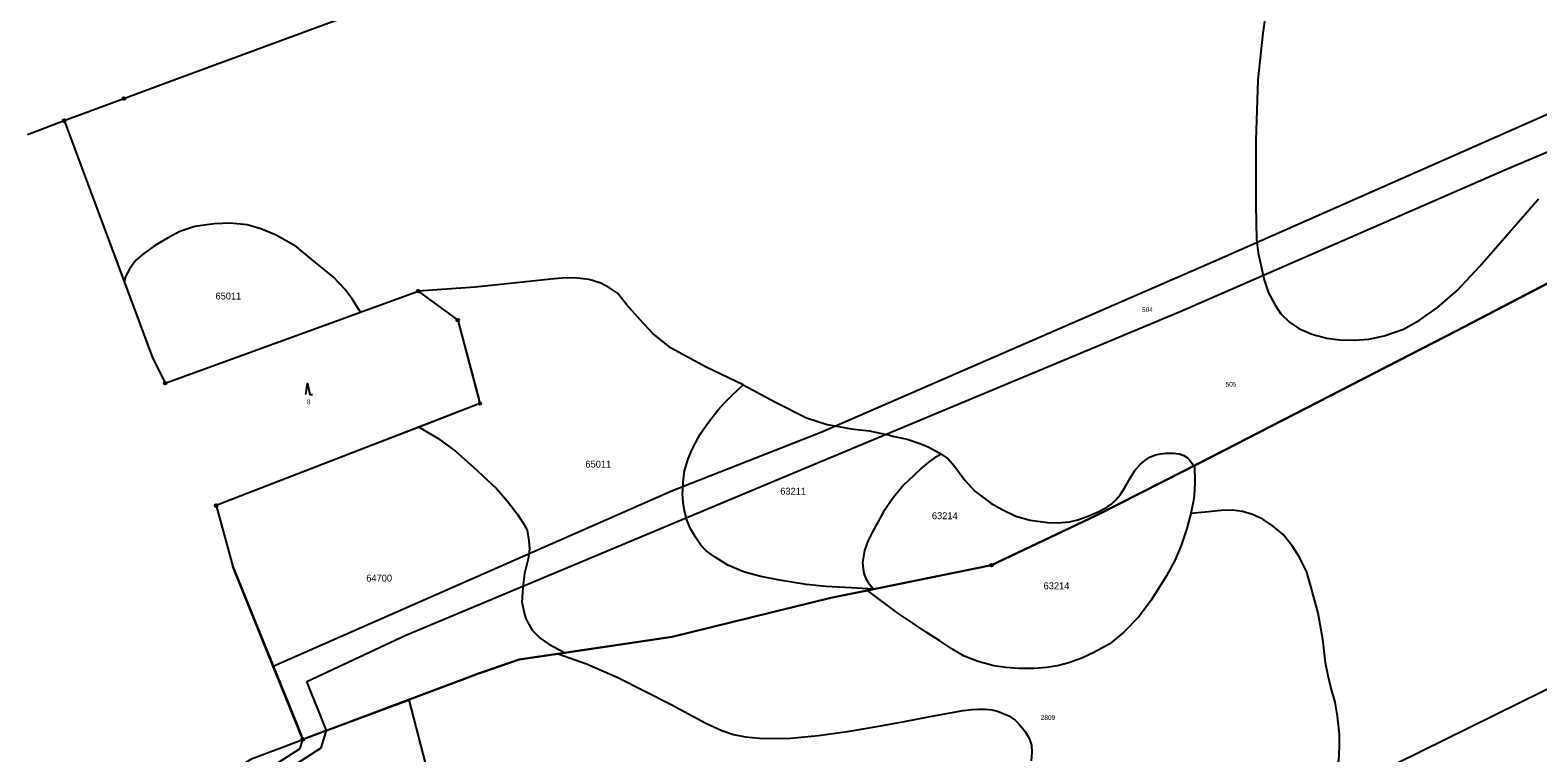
# Model space of a CAD drawing. Extents: x -546762 to -540209, y -1046851 to -1035694.
# Drawn here: x -543378 to -542834, y -1037889 to -1037629 of the extents above; entities that cross this region are included whole.
import ezdxf

# ---------------------------------------------------------------- set-up
doc = ezdxf.new("R2010")
doc.units = 0
for name, color, linetype in [('Vrstva 1', 7, 'Continuous'), ('Vrstva 13', 7, 'Continuous'), ('Vrstva 16', 7, 'Continuous'), ('Vrstva 18', 7, 'Continuous'), ('Vrstva 24', 7, 'Continuous'), ('Vrstva 25', 7, 'Continuous'), ('Vrstva 52', 7, 'Continuous'), ('Vrstva 53', 7, 'Continuous')]:
    doc.layers.add(name, color=color, linetype=linetype)

msp = doc.modelspace()

# ---------------------------------------------------------------- linework, layer by layer
at = {"layer": 'Vrstva 1'}
for points in [[(-542805.97, -1037647.97), (-542951.27, -1037712.12)], [(-543365.34, -1037661.2), (-543333.73, -1037746.28)], [(-542846.53, -1037679.1), (-542798.39, -1037658.61)], [(-542963.29, -1037729.97), (-542846.53, -1037679.1)], [(-542951.27, -1037712.12), (-543092.34, -1037773.37)], [(-543328.98, -1037755.78), (-543237.86, -1037722.64)], [(-543237.86, -1037722.64), (-543223.51, -1037733.09)], [(-543102.79, -1037788.23), (-542963.29, -1037729.97)], [(-543223.51, -1037733.09), (-543215.56, -1037763.13)], [(-543333.73, -1037746.28), (-543328.98, -1037755.78)], [(-543215.56, -1037763.13), (-543310.65, -1037799.88)], [(-543092.34, -1037773.37), (-543146.21, -1037794.52)], [(-543242.28, -1037846.48), (-543102.79, -1037788.23)], [(-543146.21, -1037794.52), (-543290.05, -1037857.78)], [(-543310.65, -1037799.88), (-543304.67, -1037821.75)], [(-543290.05, -1037857.78), (-543304.67, -1037821.75)], [(-543277.99, -1037863.18), (-543242.28, -1037846.48)], [(-543279.38, -1037884.08), (-543290.05, -1037857.78)], [(-542823.6, -1037862.41), (-542885.41, -1037892.84)], [(-543270.81, -1037880.88), (-543277.99, -1037863.18)], [(-543211.01, -1037985.66), (-543241.09, -1037869.78)], [(-543280.35, -1037887.31), (-543279.38, -1037884.08)], [(-543272.73, -1037887.17), (-543270.81, -1037880.88)], [(-543330.94, -1037919.79), (-543280.35, -1037887.31)], [(-543327.84, -1037922.56), (-543272.73, -1037887.17)]]:
    msp.add_lwpolyline(points, dxfattribs=at)
at = {"layer": 'Vrstva 13'}
for points in [[(-543327.47, -1037647.05), (-543267.73, -1037625.19)], [(-543343.92, -1037653.2), (-543327.47, -1037647.05)], [(-543365.34, -1037661.2), (-543343.92, -1037653.2)], [(-543378.65, -1037666.17), (-543365.34, -1037661.2)], [(-542863.73, -1037736.88), (-542811.28, -1037709.61)], [(-542863.73, -1037736.88), (-542811.28, -1037709.61)], [(-542863.73, -1037736.88), (-542943.06, -1037777.75)], [(-542863.73, -1037736.88), (-542943.06, -1037777.75)], [(-542943.06, -1037777.75), (-542961.6, -1037787.22)], [(-542943.06, -1037777.75), (-542961.6, -1037787.22)], [(-542961.6, -1037787.22), (-542993.59, -1037803.39)], [(-542961.6, -1037787.22), (-542993.59, -1037803.39)], [(-542993.59, -1037803.39), (-543031.22, -1037821.3)], [(-542993.59, -1037803.39), (-543031.22, -1037821.3)], [(-543031.22, -1037821.3), (-543089.11, -1037833.1)], [(-543031.22, -1037821.3), (-543089.11, -1037833.1)], [(-543089.11, -1037833.1), (-543146.35, -1037847.19)], [(-543089.11, -1037833.1), (-543146.35, -1037847.19)], [(-543146.35, -1037847.19), (-543201.5, -1037855.31)], [(-543146.35, -1037847.19), (-543201.5, -1037855.31)], [(-543201.5, -1037855.31), (-543211.84, -1037858.86)], [(-543201.5, -1037855.31), (-543211.84, -1037858.86)], [(-543216.44, -1037860.58), (-543241.09, -1037869.78)], [(-543216.44, -1037860.58), (-543241.09, -1037869.78)], [(-543213.18, -1037859.36), (-543216.44, -1037860.58)], [(-543213.18, -1037859.36), (-543216.44, -1037860.58)], [(-543211.84, -1037858.86), (-543213.18, -1037859.36)], [(-543211.84, -1037858.86), (-543213.18, -1037859.36)], [(-543270.81, -1037880.88), (-543241.09, -1037869.78)], [(-543270.81, -1037880.88), (-543241.09, -1037869.78)], [(-543297.93, -1037891.04), (-543279.38, -1037884.08)], [(-543297.93, -1037891.04), (-543279.38, -1037884.08)], [(-543270.81, -1037880.88), (-543279.38, -1037884.08)], [(-543270.81, -1037880.88), (-543279.38, -1037884.08)]]:
    msp.add_lwpolyline(points, dxfattribs=at)
at = {"layer": 'Vrstva 24'}
for centre, radius in [((-543343.92, -1037653.2), 0.5), ((-543343.92, -1037653.2), 0.1), ((-543365.34, -1037661.2), 0.5), ((-543365.34, -1037661.2), 0.1), ((-543237.86, -1037722.64), 0.5), ((-543237.86, -1037722.64), 0.1), ((-543223.51, -1037733.09), 0.5), ((-543223.51, -1037733.09), 0.1), ((-543328.98, -1037755.78), 0.5), ((-543328.98, -1037755.78), 0.1), ((-543215.56, -1037763.13), 0.5), ((-543215.56, -1037763.13), 0.1), ((-543310.65, -1037799.88), 0.5), ((-543310.65, -1037799.88), 0.1), ((-543031.22, -1037821.3), 0.5), ((-543031.22, -1037821.3), 0.1), ((-543279.38, -1037884.08), 0.5), ((-543279.38, -1037884.08), 0.1)]:
    msp.add_circle(centre, radius, dxfattribs=at)
at = {"layer": 'Vrstva 25'}
msp.add_lwpolyline([(-543278.36, -1037759.86), (-543277.66, -1037755.86), (-543276.86, -1037759.86), (-543275.86, -1037759.86)], dxfattribs=at)
at = {"layer": 'Vrstva 52'}
for points in [[(-543365.34, -1037661.2), (-543343.92, -1037653.2), (-543327.47, -1037647.05), (-543267.73, -1037625.19), (-543235.81, -1037616.25), (-543203.18, -1037606.26), (-543165.36, -1037594.45), (-543131.14, -1037580.09), (-543110.06, -1037571.25), (-543094.01, -1037561.29), (-543066.03, -1037551.41), (-543055.79, -1037547.74), (-542980.98, -1037519.01), (-542991.19, -1037498.05), (-543009.21, -1037454.54), (-543031.79, -1037392.1), (-543041.26, -1037370.55), (-543046.29, -1037359.6)], [(-542931.78, -1037618.19), (-542933.54, -1037629.67), (-542935.24, -1037646.53), (-542935.95, -1037668.36), (-542935.95, -1037691.46), (-542935.81, -1037704.07), (-542935.21, -1037708.82), (-542935.19, -1037708.92), (-542934.24, -1037713.19), (-542933.59, -1037715.88), (-542932.95, -1037718.54), (-542931.41, -1037723.24), (-542929.22, -1037727.45), (-542926.96, -1037730.85), (-542923.88, -1037733.76), (-542920.56, -1037736.03), (-542915.79, -1037738.14), (-542910.44, -1037739.51), (-542905.75, -1037740.16), (-542900.57, -1037740.32), (-542895.23, -1037739.92), (-542889.72, -1037738.7), (-542882.76, -1037736.28), (-542877.01, -1037733.12), (-542870.54, -1037728.5), (-542863.42, -1037722.43), (-542855.24, -1037713.6), (-542834.1, -1037689.32)], [(-542597.71, -1037761.19), (-542601.64, -1037747.66), (-542602.11, -1037746.04), (-542619.97, -1037671.06), (-542636.93, -1037631.27), (-542645.13, -1037634.51), (-542696.78, -1037655.45), (-542744.49, -1037676.78), (-542808.69, -1037708.26), (-542863.73, -1037736.88), (-542943.06, -1037777.75), (-542953.82, -1037783.29), (-542958.58, -1037785.7)], [(-542958.13, -1037785.47), (-542953.82, -1037783.29), (-542943.06, -1037777.75), (-542863.73, -1037736.88), (-542808.69, -1037708.26), (-542744.49, -1037676.78), (-542696.78, -1037655.45), (-542645.13, -1037634.51), (-542636.93, -1037631.27), (-542619.97, -1037671.06), (-542602.11, -1037746.04), (-542601.64, -1037747.66), (-542601.46, -1037748.27)], [(-543365.34, -1037661.2), (-543343.8, -1037719.18)], [(-543258.59, -1037730.18), (-543261.69, -1037725.27), (-543264.32, -1037721.93), (-543268.39, -1037717.53), (-543276.11, -1037711.24), (-543281.84, -1037706.54), (-543289, -1037702.4), (-543294.49, -1037700.18), (-543299.42, -1037698.74), (-543305.63, -1037698.19), (-543311.36, -1037698.34), (-543318.28, -1037699.3), (-543323.77, -1037701.13), (-543328.15, -1037703.52), (-543332.52, -1037706.07), (-543336.66, -1037709.01), (-543339.68, -1037711.64), (-543341.91, -1037714.66), (-543343.26, -1037717.37), (-543343.8, -1037719.18)], [(-543343.8, -1037719.18), (-543333.73, -1037746.28)], [(-543120.76, -1037756.4), (-543134.12, -1037750), (-543146.65, -1037743.17), (-543153.2, -1037738.02), (-543157.85, -1037732.98), (-543162.73, -1037727.41), (-543166.04, -1037723.39), (-543168.9, -1037721.47), (-543172.01, -1037719.8), (-543176.22, -1037718.45), (-543180.6, -1037717.89), (-543184.58, -1037717.81), (-543189.99, -1037718.29), (-543197.87, -1037719.17), (-543217.28, -1037721.24), (-543237.86, -1037722.64)], [(-543258.59, -1037730.18), (-543237.86, -1037722.64)], [(-543237.86, -1037722.64), (-543223.51, -1037733.09), (-543216.02, -1037761.39), (-543215.56, -1037763.13), (-543237.45, -1037771.59)], [(-543333.73, -1037746.28), (-543328.98, -1037755.78), (-543259.57, -1037730.54)], [(-543259.57, -1037730.54), (-543258.59, -1037730.18)], [(-543073.78, -1037829.98), (-543081.82, -1037829.5), (-543090.89, -1037828.95), (-543098.06, -1037828.31), (-543107.68, -1037826.78), (-543114.41, -1037825.37), (-543120.27, -1037823.83), (-543126.23, -1037821.28), (-543130.77, -1037818.5), (-543134.03, -1037816.14), (-543136.02, -1037814.07), (-543137.85, -1037811.29), (-543139.76, -1037808.18), (-543141.04, -1037805), (-543141.91, -1037801.81), (-543142.39, -1037798.79), (-543142.47, -1037797.21), (-543142.55, -1037795.52), (-543142.51, -1037794.4), (-543142.39, -1037791.38), (-543141.83, -1037787.32), (-543140.72, -1037783.34), (-543139.52, -1037780.4), (-543137.85, -1037777.21), (-543136.18, -1037774.19), (-543134.11, -1037771.01), (-543132.36, -1037768.7), (-543129.74, -1037765.35), (-543127.43, -1037762.89), (-543124.72, -1037760.1), (-543120.76, -1037756.4)], [(-543120.76, -1037756.4), (-543109.06, -1037762.67), (-543097.92, -1037768.25), (-543090.48, -1037770.71), (-543081.73, -1037772.23), (-543078.75, -1037772.55), (-543075.21, -1037772.94), (-543068.05, -1037774.54), (-543066.83, -1037774.81), (-543061.6, -1037775.97), (-543056.67, -1037777.56), (-543053.8, -1037778.83), (-543050.06, -1037780.82), (-543049.36, -1037781.31)], [(-543237.45, -1037771.59), (-543252.53, -1037777.41), (-543254.36, -1037778.12), (-543310.65, -1037799.88), (-543304.67, -1037821.75), (-543281.19, -1037879.42), (-543280.44, -1037881.35), (-543279.38, -1037884.08)], [(-543237.45, -1037771.59), (-543230.61, -1037775.69), (-543224.34, -1037780.29), (-543218.07, -1037785.86), (-543209.62, -1037793.72), (-543205.8, -1037798.1), (-543202.22, -1037802.88), (-543200.07, -1037805.9), (-543198.56, -1037808.77), (-543197.92, -1037812.59), (-543197.77, -1037815.62), (-543198.22, -1037819.08), (-543199.48, -1037824.37), (-543200.17, -1037829.39), (-543200.45, -1037834.78), (-543200.37, -1037835.16), (-543199.58, -1037839), (-543198.99, -1037840.5), (-543198.38, -1037842.02), (-543196.79, -1037844.73), (-543193.85, -1037847.68), (-543190.76, -1037849.75), (-543184.92, -1037852.87)], [(-543049.36, -1037781.31), (-543051.86, -1037782.76), (-543053.91, -1037784.26), (-543056.46, -1037786.44), (-543059.33, -1037789.14), (-543062.83, -1037792.41), (-543066.73, -1037797.1), (-543070.15, -1037802.12), (-543074.25, -1037809.61), (-543075.79, -1037812.62), (-543077.02, -1037816.03), (-543077.39, -1037818.21), (-543077.7, -1037820.35), (-543077.52, -1037822.62), (-543077.2, -1037824.35), (-543076.57, -1037826.08), (-543075.68, -1037827.58)], [(-543049.36, -1037781.31), (-543046.88, -1037783.05), (-543044.64, -1037785.64), (-543040.88, -1037790.66), (-543037.26, -1037794.7), (-543031.55, -1037799.01), (-543027.37, -1037801.24), (-543022.46, -1037803.72), (-543017.36, -1037805.13), (-543011.04, -1037805.94), (-543007.45, -1037806.03), (-543003.18, -1037805.67), (-543000.09, -1037804.94), (-542996.13, -1037803.53), (-542992.81, -1037802.08), (-542989.86, -1037800.58), (-542987.95, -1037799.21), (-542986.51, -1037797.8), (-542984.88, -1037795.98), (-542983.2, -1037793.35), (-542981.29, -1037789.93), (-542979.6, -1037787.25), (-542977.79, -1037785.16), (-542976.06, -1037783.57), (-542974.24, -1037782.43), (-542972.14, -1037781.63), (-542970.41, -1037781.22), (-542968.36, -1037780.95), (-542965.77, -1037781), (-542963.68, -1037781.27), (-542961.95, -1037781.77), (-542960.63, -1037782.63), (-542959.63, -1037783.73), (-542959, -1037784.68), (-542958.58, -1037785.7)], [(-543075.99, -1037830.43), (-543031.22, -1037821.3), (-542993.59, -1037803.39), (-542961.6, -1037787.22), (-542958.13, -1037785.47)], [(-542958.58, -1037785.7), (-542961.6, -1037787.22), (-542993.59, -1037803.39)], [(-542958.13, -1037785.47), (-542957.93, -1037791.4), (-542958.13, -1037794.31), (-542958.35, -1037797.47), (-542959.38, -1037802.68)], [(-542959.38, -1037802.68), (-542960.83, -1037808.06), (-542962.88, -1037814.21), (-542965.18, -1037819.67), (-542968.25, -1037825.18), (-542973.72, -1037833.98), (-542978.15, -1037839.95), (-542983.62, -1037845.51), (-542988.65, -1037849.69), (-542994.37, -1037852.76), (-542998.73, -1037854.81), (-543003.42, -1037856.52), (-543007.43, -1037857.55), (-543011.44, -1037858.14), (-543015.71, -1037858.49)], [(-542910.86, -1037856.45), (-542911.65, -1037849.99), (-542911.88, -1037848.13), (-542913.5, -1037838.57), (-542915.55, -1037831.22), (-542915.85, -1037830.17), (-542916.79, -1037826.89), (-542917.68, -1037823.79), (-542920.16, -1037818.67), (-542922.93, -1037814.35), (-542926.17, -1037810.33), (-542930.18, -1037807), (-542933.51, -1037804.7), (-542937.18, -1037803.07), (-542939.6, -1037802.34), (-542940.85, -1037801.96), (-542944.44, -1037801.54), (-542948.53, -1037801.62), (-542954.28, -1037802.18), (-542959.38, -1037802.68)], [(-542993.59, -1037803.39), (-543031.22, -1037821.3), (-543073.78, -1037829.98)], [(-543073.78, -1037829.98), (-543089.11, -1037833.1), (-543146.35, -1037847.19)], [(-543075.68, -1037827.58), (-543073.78, -1037829.98)], [(-543187.38, -1037853.23), (-543146.35, -1037847.19), (-543089.11, -1037833.1), (-543075.99, -1037830.43)], [(-543015.71, -1037858.49), (-543021.51, -1037858.49), (-543026.04, -1037858.14), (-543030.39, -1037857.55), (-543036.02, -1037856.01), (-543041.06, -1037854.05), (-543045.16, -1037851.74), (-543049.85, -1037848.58), (-543054.8, -1037845.42), (-543059.58, -1037842.17), (-543064.96, -1037838.57), (-543075.99, -1037830.43)], [(-543146.35, -1037847.19), (-543184.92, -1037852.87)], [(-543369.01, -1037935.63), (-543351.03, -1037924.46), (-543297.93, -1037891.04), (-543279.38, -1037884.08), (-543279.31, -1037884.06), (-543220.18, -1037861.88), (-543216.43, -1037860.52), (-543213.17, -1037859.34), (-543211.84, -1037858.86), (-543201.5, -1037855.31), (-543187.38, -1037853.23)], [(-543184.92, -1037852.87), (-543201.5, -1037855.31), (-543211.84, -1037858.86), (-543213.17, -1037859.34), (-543216.43, -1037860.52), (-543220.18, -1037861.88), (-543279.38, -1037884.08)], [(-543187.38, -1037853.23), (-543177.18, -1037856.9), (-543166.1, -1037861.66), (-543155.94, -1037866.79), (-543146.64, -1037871.57), (-543134.18, -1037878.23), (-543128.37, -1037880.88), (-543124.19, -1037882.33), (-543119.84, -1037883.18), (-543114.89, -1037883.7), (-543110.37, -1037883.78), (-543103.62, -1037883.61), (-543093.61, -1037882.63), (-543083.16, -1037881.28), (-543071.8, -1037879.34), (-543061.95, -1037877.55), (-543051.49, -1037875.46), (-543041.48, -1037873.66), (-543038.31, -1037873.29), (-543035.92, -1037873.14), (-543033.39, -1037873.14), (-543031.14, -1037873.44), (-543029.05, -1037873.97), (-543027, -1037874.75), (-543025.26, -1037875.5), (-543024.95, -1037875.63), (-543022.87, -1037877.08), (-543021.24, -1037878.61), (-543019.24, -1037881.1), (-543017.63, -1037883.68), (-543016.8, -1037886.12), (-543016.66, -1037888.71), (-543016.9, -1037891.78)], [(-542913.31, -1037912.03), (-542911.5, -1037908.22), (-542909.21, -1037903.4), (-542909.05, -1037902.95), (-542907.25, -1037897.94), (-542907.16, -1037897.44), (-542906.05, -1037891.62), (-542905.8, -1037886.84), (-542905.82, -1037882.25), (-542906.59, -1037875.67), (-542907.44, -1037870.63), (-542908.98, -1037865.25), (-542910, -1037861.15), (-542910.86, -1037856.45)]]:
    msp.add_lwpolyline(points, dxfattribs=at)

# ---------------------------------------------------------------- texts
at = {"layer": 'Vrstva 16'}
msp.add_text('8', height=1.7, dxfattribs=at).set_placement((-543277.94, -1037763.38))
at = {"layer": 'Vrstva 18'}
for s, p in [('504', (-542977, -1037730.15)), ('505', (-542946.91, -1037757.03)), ('2809', (-543013.51, -1037877.06))]:
    msp.add_text(s, height=1.7, dxfattribs=at).set_placement(p)
at = {"layer": 'Vrstva 53'}
for s, p in [('65011', (-543310.88, -1037725.63)), ('65011', (-543177.58, -1037786.18)), ('63211', (-543107.37, -1037795.93)), ('63214', (-543052.73, -1037804.76)), ('64700', (-543256.54, -1037827.23)), ('63214', (-543012.48, -1037830.01))]:
    msp.add_text(s, height=2.5, dxfattribs=at).set_placement(p)

doc.saveas('drawing.dxf')
